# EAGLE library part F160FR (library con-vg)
CONNECTOR female, 160 pins, type R, rows ABCDE, grid 2.54 mm
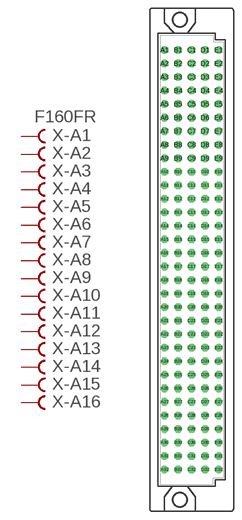
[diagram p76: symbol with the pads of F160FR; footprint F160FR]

Designator prefix X; gates -A1=FVAL -A2=FEM -A3=FEM -A4=FEM -A5=FEM -A6=FEM -A7=FEM -A8=FEM -A9=FEM -A10=FEM -A11=FEM -A12=FEM -A13=FEM -A14=FEM -A15=FEM -A16=FEM -A17=FEM -A18=FEM -A19=FEM -A20=FEM -A21=FEM -A22=FEM -A23=FEM -A24=FEM -A25=FEM -A26=FEM -A27=FEM -A28=FEM -A29=FEM -A30=FEM -A31=FEM -A32=FEM -B1=FVAL -B2=FEM -B3=FEM -B4=FEM -B5=FEM -B6=FEM -B7=FEM -B8=FEM -B9=FEM -B10=FEM -B11=FEM -B12=FEM -B13=FEM -B14=FEM -B15=FEM -B16=FEM -B17=FEM -B18=FEM -B19=FEM -B20=FEM -B21=FEM -B22=FEM -B23=FEM -B24=FEM -B25=FEM -B26=FEM -B27=FEM -B28=FEM -B29=FEM -B30=FEM -B31=FEM -B32=FEM -C1=FVAL -C2=FEM -C3=FEM -C4=FEM -C5=FEM -C6=FEM -C7=FEM -C8=FEM -C9=FEM -C10=FEM -C11=FEM -C12=FEM -C13=FEM -C14=FEM -C15=FEM -C16=FEM -C17=FEM -C18=FEM -C19=FEM -C20=FEM -C21=FEM -C22=FEM -C23=FEM -C24=FEM -C25=FEM -C26=FEM -C27=FEM -C28=FEM -C29=FEM -C30=FEM -C31=FEM -C32=FEM -D1=FVAL -D2=FEM -D3=FEM -D4=FEM -D5=FEM -D6=FEM -D7=FEM -D8=FEM -D9=FEM -D10=FEM -D11=FEM -D12=FEM -D13=FEM -D14=FEM -D15=FEM -D16=FEM -D17=FEM -D18=FEM -D19=FEM -D20=FEM -D21=FEM -D22=FEM -D23=FEM -D24=FEM -D25=FEM -D26=FEM -D27=FEM -D28=FEM -D29=FEM -D30=FEM -D31=FEM -D32=FEM -E1=FVAL -E2=FEM -E3=FEM -E4=FEM -E5=FEM -E6=FEM -E7=FEM -E8=FEM -E9=FEM -E10=FEM -E11=FEM -E12=FEM -E13=FEM -E14=FEM -E15=FEM -E16=FEM -E17=FEM -E18=FEM -E19=FEM -E20=FEM -E21=FEM -E22=FEM -E23=FEM -E24=FEM -E25=FEM -E26=FEM -E27=FEM -E28=FEM -E29=FEM -E30=FEM -E31=FEM -E32=FEM

## F160FR  [F160FR]
A1  -A1:B  pas
A2  -A2:B  pas
A3  -A3:B  pas
A4  -A4:B  pas
A5  -A5:B  pas
A6  -A6:B  pas
A7  -A7:B  pas
A8  -A8:B  pas
A9  -A9:B  pas
A10  -A10:B  pas
A11  -A11:B  pas
A12  -A12:B  pas
A13  -A13:B  pas
A14  -A14:B  pas
A15  -A15:B  pas
A16  -A16:B  pas
A17  -A17:B  pas
A18  -A18:B  pas
A19  -A19:B  pas
A20  -A20:B  pas
A21  -A21:B  pas
A22  -A22:B  pas
A23  -A23:B  pas
A24  -A24:B  pas
A25  -A25:B  pas
A26  -A26:B  pas
A27  -A27:B  pas
A28  -A28:B  pas
A29  -A29:B  pas
A30  -A30:B  pas
A31  -A31:B  pas
A32  -A32:B  pas
B1  -B1:B  pas
B2  -B2:B  pas
B3  -B3:B  pas
B4  -B4:B  pas
B5  -B5:B  pas
B6  -B6:B  pas
B7  -B7:B  pas
B8  -B8:B  pas
B9  -B9:B  pas
B10  -B10:B  pas
B11  -B11:B  pas
B12  -B12:B  pas
B13  -B13:B  pas
B14  -B14:B  pas
B15  -B15:B  pas
B16  -B16:B  pas
B17  -B17:B  pas
B18  -B18:B  pas
B19  -B19:B  pas
B20  -B20:B  pas
B21  -B21:B  pas
B22  -B22:B  pas
B23  -B23:B  pas
B24  -B24:B  pas
B25  -B25:B  pas
B26  -B26:B  pas
B27  -B27:B  pas
B28  -B28:B  pas
B29  -B29:B  pas
B30  -B30:B  pas
B31  -B31:B  pas
B32  -B32:B  pas
C1  -C1:B  pas
C2  -C2:B  pas
C3  -C3:B  pas
C4  -C4:B  pas
C5  -C5:B  pas
C6  -C6:B  pas
C7  -C7:B  pas
C8  -C8:B  pas
C9  -C9:B  pas
C10  -C10:B  pas
C11  -C11:B  pas
C12  -C12:B  pas
C13  -C13:B  pas
C14  -C14:B  pas
C15  -C15:B  pas
C16  -C16:B  pas
C17  -C17:B  pas
C18  -C18:B  pas
C19  -C19:B  pas
C20  -C20:B  pas
C21  -C21:B  pas
C22  -C22:B  pas
C23  -C23:B  pas
C24  -C24:B  pas
C25  -C25:B  pas
C26  -C26:B  pas
C27  -C27:B  pas
C28  -C28:B  pas
C29  -C29:B  pas
C30  -C30:B  pas
C31  -C31:B  pas
C32  -C32:B  pas
D1  -D1:B  pas
D2  -D2:B  pas
D3  -D3:B  pas
D4  -D4:B  pas
D5  -D5:B  pas
D6  -D6:B  pas
D7  -D7:B  pas
D8  -D8:B  pas
D9  -D9:B  pas
D10  -D10:B  pas
D11  -D11:B  pas
D12  -D12:B  pas
D13  -D13:B  pas
D14  -D14:B  pas
D15  -D15:B  pas
D16  -D16:B  pas
D17  -D17:B  pas
D18  -D18:B  pas
D19  -D19:B  pas
D20  -D20:B  pas
D21  -D21:B  pas
D22  -D22:B  pas
D23  -D23:B  pas
D24  -D24:B  pas
D25  -D25:B  pas
D26  -D26:B  pas
D27  -D27:B  pas
D28  -D28:B  pas
D29  -D29:B  pas
D30  -D30:B  pas
D31  -D31:B  pas
D32  -D32:B  pas
E1  -E1:B  pas
E2  -E2:B  pas
E3  -E3:B  pas
E4  -E4:B  pas
E5  -E5:B  pas
E6  -E6:B  pas
E7  -E7:B  pas
E8  -E8:B  pas
E9  -E9:B  pas
E10  -E10:B  pas
E11  -E11:B  pas
E12  -E12:B  pas
E13  -E13:B  pas
E14  -E14:B  pas
E15  -E15:B  pas
E16  -E16:B  pas
E17  -E17:B  pas
E18  -E18:B  pas
E19  -E19:B  pas
E20  -E20:B  pas
E21  -E21:B  pas
E22  -E22:B  pas
E23  -E23:B  pas
E24  -E24:B  pas
E25  -E25:B  pas
E26  -E26:B  pas
E27  -E27:B  pas
E28  -E28:B  pas
E29  -E29:B  pas
E30  -E30:B  pas
E31  -E31:B  pas
E32  -E32:B  pas

## Footprint F160FR (pad centres in mm)
CONNECTOR female, 160 pins, type R, rows ABCDE, grid 2.54 mm
drill 0.914 octagon: A1 -2.54,39.37; A2 -2.54,36.83; A3 -2.54,34.29; A4 -2.54,31.75; A5 -2.54,29.21; A6 -2.54,26.67; A7 -2.54,24.13; A8 -2.54,21.59; A9 -2.54,19.05; A10 -2.54,16.51; A11 -2.54,13.97; A12 -2.54,11.43; A13 -2.54,8.89; A14 -2.54,6.35; A15 -2.54,3.81; A16 -2.54,1.27; A17 -2.54,-1.27; A18 -2.54,-3.81; A19 -2.54,-6.35; A20 -2.54,-8.89; A21 -2.54,-11.43; A22 -2.54,-13.97; A23 -2.54,-16.51; A24 -2.54,-19.05; A25 -2.54,-21.59; A26 -2.54,-24.13; A27 -2.54,-26.67; A28 -2.54,-29.21; A29 -2.54,-31.75; A30 -2.54,-34.29; A31 -2.54,-36.83; A32 -2.54,-39.37; B1 0,39.37; B2 0,36.83; B3 0,34.29; B4 0,31.75; B5 0,29.21; B6 0,26.67; B7 0,24.13; B8 0,21.59; B9 0,19.05; B10 0,16.51; B11 0,13.97; B12 0,11.43; B13 0,8.89; B14 0,6.35; B15 0,3.81; B16 0,1.27; B17 0,-1.27; B18 0,-3.81; B19 0,-6.35; B20 0,-8.89; B21 0,-11.43; B22 0,-13.97; B23 0,-16.51; B24 0,-19.05; B25 0,-21.59; B26 0,-24.13; B27 0,-26.67; B28 0,-29.21; B29 0,-31.75; B30 0,-34.29; B31 0,-36.83; B32 0,-39.37; C1 2.54,39.37; C2 2.54,36.83; C3 2.54,34.29; C4 2.54,31.75; C5 2.54,29.21; C6 2.54,26.67; C7 2.54,24.13; C8 2.54,21.59; C9 2.54,19.05; C10 2.54,16.51; C11 2.54,13.97; C12 2.54,11.43; C13 2.54,8.89; C14 2.54,6.35; C15 2.54,3.81; C16 2.54,1.27; C17 2.54,-1.27; C18 2.54,-3.81; C19 2.54,-6.35; C20 2.54,-8.89; C21 2.54,-11.43; C22 2.54,-13.97; C23 2.54,-16.51; C24 2.54,-19.05; C25 2.54,-21.59; C26 2.54,-24.13; C27 2.54,-26.67; C28 2.54,-29.21; C29 2.54,-31.75; C30 2.54,-34.29; C31 2.54,-36.83; C32 2.54,-39.37; D1 5.08,39.37; D2 5.08,36.83; D3 5.08,34.29; D4 5.08,31.75; D5 5.08,29.21; D6 5.08,26.67; D7 5.08,24.13; D8 5.08,21.59; D9 5.08,19.05; D10 5.08,16.51; D11 5.08,13.97; D12 5.08,11.43; D13 5.08,8.89; D14 5.08,6.35; D15 5.08,3.81; D16 5.08,1.27; D17 5.08,-1.27; D18 5.08,-3.81; D19 5.08,-6.35; D20 5.08,-8.89; D21 5.08,-11.43; D22 5.08,-13.97; D23 5.08,-16.51; D24 5.08,-19.05; D25 5.08,-21.59; D26 5.08,-24.13; D27 5.08,-26.67; D28 5.08,-29.21; D29 5.08,-31.75; D30 5.08,-34.29; D31 5.08,-36.83; D32 5.08,-39.37; E1 7.62,39.37; E2 7.62,36.83; E3 7.62,34.29; E4 7.62,31.75; E5 7.62,29.21; E6 7.62,26.67; E7 7.62,24.13; E8 7.62,21.59; E9 7.62,19.05; E10 7.62,16.51; E11 7.62,13.97; E12 7.62,11.43; E13 7.62,8.89; E14 7.62,6.35; E15 7.62,3.81; E16 7.62,1.27; E17 7.62,-1.27; E18 7.62,-3.81; E19 7.62,-6.35; E20 7.62,-8.89; E21 7.62,-11.43; E22 7.62,-13.97; E23 7.62,-16.51; E24 7.62,-19.05; E25 7.62,-21.59; E26 7.62,-24.13; E27 7.62,-26.67; E28 7.62,-29.21; E29 7.62,-31.75; E30 7.62,-34.29; E31 7.62,-36.83; E32 7.62,-39.37
hole 2.794 at 0.305,45.009
hole 2.794 at 0.305,-45.009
